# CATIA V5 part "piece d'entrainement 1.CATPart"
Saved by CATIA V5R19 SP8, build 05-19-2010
Part number: piece d'entrainement 1
Bounding box of the stored display mesh (mm): x -59.975 to 59.975, y 0 to 550, z -59.975 to 59.975
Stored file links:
  G:\EU_thinkMotion\CFAO_2010\MMS_groupe2\MMS_groupe2\A reprendre\splanchenault\Planchenault\piece d'entrainement 1.CATPart
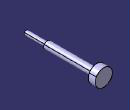
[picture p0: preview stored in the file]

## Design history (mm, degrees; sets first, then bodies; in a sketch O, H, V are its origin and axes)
Body1 (main body)
  Sketch1 on xy-plane, origin (0, 0, 0), H (1, 0, 0), V (0, 1, 0)
    line L1 (0, 0) -> (15, 0)
    line L2 (15, 0) -> (15, 150)
    line L3 (15, 150) -> (25, 150)
    line L4 (25, 150) -> (25, 500)
    line L5 (25, 500) -> (60, 500)
    line L6 (60, 500) -> (60, 550)
    line L7 (60, 550) -> (0, 550)
    line L8 (0, 550) -> (0, 0)
    length L1 = 15
    length L3 = 10
    length L2 = 150
    length L4 = 350
    length L8 = 550
    length L5 = 35
    horizontal: L1 H, L3 H, L5 H, L7 H
    vertical: L2 V, L4 V, L6 V, L8 V
  Shaft1: profile Sketch1, axis Sketch1.L8, angle 360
